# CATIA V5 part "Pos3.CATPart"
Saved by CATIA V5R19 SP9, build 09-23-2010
Part number: Pos3
Bounding box of the stored display mesh (mm): x 0 to 1350, y -25 to 25, z -50 to 50
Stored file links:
  D:\UG\Beispiel\R19\Produkt_ZSB\Pos3.CATPart
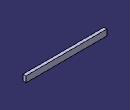
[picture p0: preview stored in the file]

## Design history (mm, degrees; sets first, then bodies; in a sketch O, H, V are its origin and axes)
AxisSystem1: origin (0, 0, 0), X (1, 0, 0), Y (0, 1, 0), Z (0, 0, 1)
Body1 (main body)
  Sketch1 on YZ plane of AxisSystem1, origin (0, 0, 0), H (0, 1, 0), V (0, 0, 1)
    line L1 (-25, 50) -> (25, 50)
    line L2 (25, 50) -> (25, -50)
    line L3 (25, -50) -> (-25, -50)
    line L4 (-25, -50) -> (-25, 50)
    distance L1 L3 = 100
    length L3 = 50
    horizontal: L1 H, L3 H
    vertical: L2 V, L4 V
    symmetry: L4 L2 V, L1 L3 H
  Pad1: profile Sketch1, direction (1, 0, 0), length 1350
